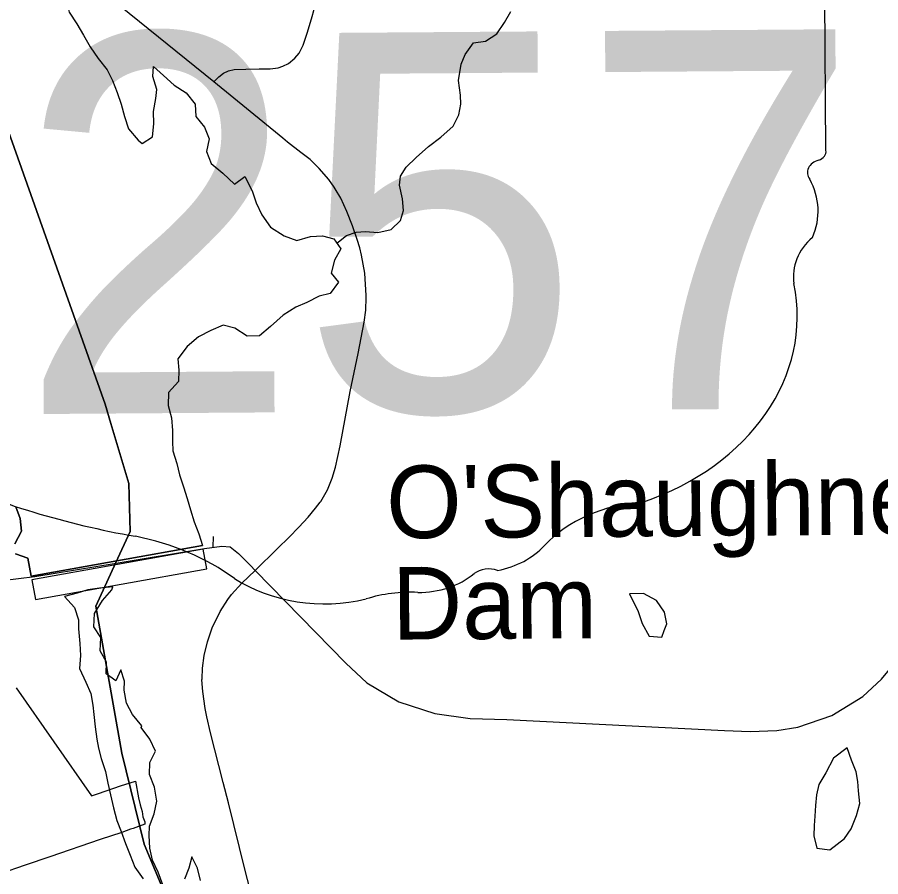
# Model space of a CAD drawing. Extents: x 114604 to 551442, y 316898 to 567001.
# Drawn here: x 170319 to 175079, y 455101 to 459836 of the extents above; entities that cross this region are included whole.
import ezdxf

# ---------------------------------------------------------------- set-up
doc = ezdxf.new("R2010")
doc.units = 0
for name, color, linetype in [('_CIVIL_CONSTRUCTION', 7, 'Continuous'), ('BD_X_Building', 7, 'Continuous'), ('DV_X_County_Line', 7, 'Continuous'), ('GE_P_Alignment_1000_Cardinal_Points', 7, 'Continuous'), ('GE_P_Alignment_100_Stations', 7, 'Continuous'), ('GE_P_Alignment_500_Bearings', 7, 'Continuous'), ('GE_P_Alignment_500_Curve_Data', 7, 'Continuous'), ('GE_P_Alignment_500_Distances', 7, 'Continuous'), ('MT_X_Edge_Line', 7, 'Continuous'), ('PM_P_Cells', 7, 'Continuous'), ('RD_X_GR_Lt', 7, 'Continuous'), ('RD_X_GR_Rt', 7, 'Continuous'), ('VG_X_Tree_Line_Lt', 7, 'Continuous')]:
    doc.layers.add(name, color=color, linetype=linetype)

msp = doc.modelspace()

# ---------------------------------------------------------------- linework, layer by layer
at = {"layer": '_CIVIL_CONSTRUCTION'}
for points in [[(171809.5, 459148.5), (171783.9, 459168.8), (171402.2, 459479.2), (170888.9, 459895.5), (170834.9, 459938.9), (170817.5, 459954.2), (170801.2, 459970.7), (170786.2, 459988.3), (170759.8, 460026.4), (170738.9, 460067.8), (170730.7, 460089.4), (170724, 460111.6), (170718.8, 460134.2), (170697.1, 460524.6)], [(171934, 459051.6), (171882.2, 459090.8), (171809.5, 459148.5)], [(172072.5, 458891), (172067, 458900.2), (172037.4, 458941.2), (171983.2, 459003.3), (171938, 459048.6), (171934, 459051.6)], [(172242.7, 458292.6), (172243.2, 458303.4), (172236, 458425.3), (172216.1, 458524.2), (172207.5, 458565.2), (172193.4, 458610.6), (172167, 458686.6), (172136.9, 458765.9), (172102.9, 458839.9), (172072.5, 458891)], [(171992.6, 457168.6), (172030, 457232.4), (172055.2, 457296), (172073, 457357.1), (172099.1, 457475.1), (172154.2, 457774), (172199.3, 457983.3), (172232, 458156.2), (172240, 458222.2), (172242.7, 458292.6)], [(171630.2, 456788), (172131.2, 456277.9), (172246.5, 456168.6), (172422.5, 456064.3), (172620.6, 456000.6), (172816.3, 455972.8), (173018.5, 455967.5), (174218.4, 455906.5), (174360, 455900.8), (174506, 455906.3), (174622.6, 455925.2), (174808.6, 455989.4), (174980.8, 456094), (175083.5, 456189.1), (175188.2, 456315.6), (175239.1, 456408.1), (175305.4, 456565.8), (175338.2, 456694.1), (175366.2, 456860.5), (175458.4, 457463.2), (175484.3, 457607.1), (175516.9, 457757.9), (175583.1, 457935.8), (175631, 458018.4)], [(171630.2, 456788), (171754.6, 456909.4), (171817.6, 456971.1), (171872.2, 457026.6), (171923.3, 457081), (171963, 457130.5), (171989.9, 457164.1), (171992.6, 457168.6)], [(171337.7, 456190.6), (171339.7, 456249.1), (171350.1, 456319.1), (171368.7, 456394.7), (171394.6, 456471.5), (171437.1, 456561.2), (171480.4, 456628.7), (171500.4, 456655), (171556.7, 456717), (171630.2, 456788)], [(171365, 455981), (171355.1, 456027.4), (171341.8, 456121.6), (171337.5, 456185.3), (171337.7, 456190.6)], [(171454.9, 455620.2), (171383.7, 455893.4), (171365, 455981)], [(172785.3, 451744.5), (172762.2, 451787.7), (172544.6, 452270.4), (172423.6, 452624.8), (172267.6, 453051), (172114.7, 453480), (172037.4, 453708.8), (171899.4, 454074.1), (171677.8, 454736.5), (171574.2, 455142.8), (171484.5, 455506.8), (171454.9, 455620.2)]]:
    msp.add_lwpolyline(points, dxfattribs=at)
at = {"layer": 'DV_X_County_Line'}
msp.add_line((170396.1, 456755.8), (171341.2, 456925), dxfattribs=at)
for points in [[(170431.1, 460604.1), (170469.3, 460538), (170501.6, 460472), (170471.8, 460401.8), (170463.9, 460351.6), (170474.1, 460287.5), (170508.4, 460219.5), (170560.7, 460155.5), (170591, 460095.4), (170597.1, 460045.3), (170591.3, 459983.2), (170589.4, 459931.1), (170605.7, 459863), (170647.9, 459799), (170684.2, 459736.9), (170720.5, 459672.9), (170764.8, 459608.9), (170815.1, 459546.9), (170843.4, 459486.8), (170869.6, 459420.8), (170891.9, 459356.7), (170910.1, 459288.6), (170932.4, 459220.5), (170986.7, 459158.5)], [(170986.7, 459158.5), (171007.9, 459140.1), (171064.4, 459176.1), (171072.9, 459248.2), (171069.4, 459316.3), (171084, 459388.4), (171088.4, 459438.5), (171066.9, 459508.8), (171069.4, 459564.9), (171125, 459514.3), (171184.7, 459461.7), (171250.5, 459419.1), (171300, 459356.6), (171303.5, 459288.4), (171351.1, 459230), (171376.6, 459165.6), (171362.1, 459095.6), (171387.6, 459029.2), (171453.3, 458976.6), (171516.9, 458916), (171573.2, 458957.6), (171614.7, 458879.1), (171636.2, 458812.8), (171667.7, 458746.4), (171715.2, 458679.9), (171791, 458631.2), (171860.8, 458606.6), (171935.1, 458628.1), (172001.2, 458631.6), (172065.2, 458615), (172102.8, 458560.6), (172068.2, 458496.7), (172049.7, 458426.7), (172089.3, 458376.3), (172044.8, 458314.5), (171982.6, 458299), (171916.2, 458263.4), (171854, 458237.9), (171785.6, 458194.3), (171715, 458132.7), (171654.5, 458081.1), (171586.4, 458079.6), (171518.7, 458122.3), (171454.7, 458138.8), (171386.4, 458109.3), (171318.1, 458075.7), (171255.6, 458022.1), (171205, 457954.4), (171210.5, 457892.2), (171208, 457828.1), (171153.5, 457768.4), (171150.9, 457696.2), (171170.4, 457627.9), (171175.9, 457559.7), (171175.4, 457497.6), (171177, 457447.5), (171198.5, 457377.2), (171214.1, 457314.9), (171235.6, 457248.6), (171255.1, 457184.3), (171274.6, 457122), (171294.1, 457055.7), (171319.7, 456989.3), (171341.2, 456925)], [(170310.8, 457138.4), (170335, 457074.4), (170343.2, 457004.2), (170305.3, 456934)], [(170309.5, 456879.9), (170377.8, 456856), (170396.1, 456755.8)], [(170845.5, 456696.8), (170773.3, 456690.6), (170709.1, 456680.5), (170649, 456662.3), (170578.9, 456644), (170635.2, 456584.1), (170657.5, 456516), (170657.6, 456465.9), (170663.9, 456385.7), (170668.1, 456319.6), (170662.3, 456247.4), (170696.6, 456173.3), (170724.9, 456109.2), (170735.1, 456045.1), (170741.2, 455995), (170749.4, 455926.9), (170757.7, 455858.8), (170767.8, 455808.7), (170782, 455752.6), (170806.3, 455680.5), (170818.5, 455616.4), (170832.8, 455552.3), (170849, 455480.2), (170867.3, 455410.1), (170891.5, 455350), (170915.7, 455283.9), (170942, 455219.8), (170968.3, 455153.8), (171012.6, 455089.7)], [(171006.1, 455931.6), (170953.8, 455993.6), (170921.5, 456057.6), (170909.3, 456127.8), (170911.1, 456177.9), (170890.9, 456240), (170863, 456179.8), (170808.8, 456217.7), (170810.6, 456281.8), (170776.3, 456345.9), (170780.1, 456418.1), (170741.8, 456478.1), (170745.6, 456550.3), (170789.5, 456622.5), (170841.5, 456680.8), (170845.5, 456696.8)], [(171122.4, 455056.6), (171096.9, 455125), (171065.4, 455191.4), (171049.9, 455257.7), (171046.4, 455327.8), (171048.8, 455379.9), (171073.4, 455447.9), (171087.9, 455515.9), (171076.5, 455594.2), (171049.1, 455664.6), (171049.6, 455730.7), (171082.1, 455792.6), (171050.6, 455859), (171003, 455923.5), (171006.1, 455931.6)], [(171328.8, 455079.1), (171313.3, 455147.3), (171281.8, 455209.7), (171265.3, 455147.7), (171240.8, 455087.8)]]:
    msp.add_lwpolyline(points, dxfattribs=at)
at = {"layer": 'GE_P_Alignment_1000_Cardinal_Points'}
msp.add_lwpolyline([(171402.2, 459479.2), (171430.6, 459508.2), (171455.5, 459527.3), (171483.7, 459540.9), (171514.1, 459548.6), (171579.1, 459550.6), (171652.6, 459551.3), (171714.3, 459550.8), (171758.4, 459556.9), (171783.7, 459565.5), (171815.3, 459581.9), (171850.1, 459609.6), (171872.7, 459637.2), (171896, 459682.7), (171918.4, 459753.1), (171945.3, 459840.1), (171953.4, 459873.5), (171964.8, 459941.4), (171969.7, 459998.3), (171969.9, 460122.1), (171978.5, 460457.7)], dxfattribs=at)
at = {"layer": 'GE_P_Alignment_100_Stations'}
msp.add_lwpolyline([(170314, 456140.8), (170727.8, 455546.8), (170728.1, 455546.3), (170767, 455559.7), (170887.9, 455601.5), (170970.5, 455627.5), (170987.8, 455534.9), (170997.1, 455497.2), (171007.1, 455460), (171011.8, 455429.9), (171021.7, 455402.6), (171022.8, 455389.3), (170957.7, 455366.8), (170943.7, 455362), (170895.5, 455345), (170775.5, 455305.6), (170499, 455211), (170363.3, 455164.7), (170225, 455117)], dxfattribs=at)
at = {"layer": 'GE_P_Alignment_500_Bearings'}
msp.add_lwpolyline([(168892.8, 456835.9), (169086.8, 456871.2), (169153.8, 456873), (169210.6, 456865.6), (169267.4, 456850.6), (169675.4, 456719.5), (169819.8, 456701.2), (169876.5, 456696.4), (169988.1, 456699.6), (170038.5, 456705.7), (170236.3, 456733.2), (170416.9, 456754.6), (170863.8, 456828.5), (171352.1, 456909.3), (171447.7, 456922.6), (171492.9, 456917.5), (171539.3, 456880.8), (171604.8, 456814.4), (171630.2, 456788)], dxfattribs=at)
at = {"layer": 'GE_P_Alignment_500_Curve_Data'}
for p, q in [((174777.2, 459102.2), (174765.3, 460760.4)), ((174776.7, 459102.6), (174777.2, 459102.2))]:
    msp.add_line(p, q, dxfattribs=at)
for centre, major_axis, start_param, end_param in [((174715.3, 459095.3), (62.2, 0.4), 5.05454, 6.418171), ((174764.7, 458980.3), (89.9, 0.6), 1.883978, 3.671073), ((174194, 458766.6), (539.9, 3.9), 5.934695, 6.695948), ((174990.4, 458409.7), (392.8, 2.8), 2.387724, 3.262537), ((173234.2, 458186.1), (1384.8, 10), 5.101753, 6.440018), ((171834, 460101.4), (3998, 28.8), 4.195995, 4.488959), ((173829.9, 456560.5), (758.4, 5.5), 1.647645, 2.488433), ((170671.5, 456003.6), (1250.9, 9), 0.823519, 1.323588), ((172864.8, 457136.3), (447.4, 3.2), 4.937069, 5.64225), ((172918.7, 456700.9), (119.1, 0.9), 1.147584, 2.315152), ((172015.6, 457238.8), (793.8, 5.7), 4.026481, 4.996735), ((172533.9, 457005.2), (422.9, 3), 4.691044, 5.507374), ((172482.1, 456146.2), (652.2, 4.7), 1.495662, 1.94098)]:
    msp.add_ellipse(centre, major_axis=major_axis, ratio=0.8, start_param=start_param, end_param=end_param, dxfattribs=at)
at = {"layer": 'GE_P_Alignment_500_Distances'}
for points in [[(170250.2, 459264.1), (170803.8, 457703.8), (170835.4, 457597.7), (170933.5, 457267.5), (170941.5, 457002.9), (170862.6, 456831.3), (170751.7, 456590.3), (170896.2, 455781.1), (171019, 455280.7), (171414.9, 454330.3), (171495.6, 453944.8), (171686.4, 453391.5), (171797.2, 453111.3), (172158.3, 452814.9), (172277.6, 452609.1), (172388.6, 452309), (172410.3, 452073.5), (172371.6, 451741.9), (171021.2, 451864.1), (170446.5, 451909.5), (169613.4, 451967.6)], [(180912.9, 451416.4), (178654.1, 451485.6), (177080.5, 451574.7), (176495.7, 451600.3), (175244.6, 451642.6), (172784.1, 451747.3), (172371.6, 451741.9), (172410.3, 452073.5), (172388.6, 452309), (172277.6, 452609.1), (172158.3, 452814.9), (171797.2, 453111.3), (171686.4, 453391.5), (171495.6, 453944.8), (171414.9, 454330.3), (171019, 455280.7), (170896.2, 455781.1), (170751.7, 456590.3), (170862.6, 456831.3), (170941.5, 457002.9), (170933.5, 457267.5), (170835.4, 457597.7), (170803.8, 457703.8), (170250.2, 459264.1)]]:
    msp.add_lwpolyline(points, dxfattribs=at)
at = {"layer": 'MT_X_Edge_Line'}
for points in [[(173886.1, 456456.2), (173900.1, 456493.9), (173887.6, 456557.9), (173843.1, 456621.8), (173770.9, 456661.3), (173694.9, 456658.8)], [(173694.9, 456658.8), (173741.7, 456560.9), (173764.2, 456495), (173802.7, 456425.1), (173872.7, 456419.6), (173886.1, 456456.2)], [(174894.5, 455811.5), (174819, 455752.9), (174775.7, 455672.5), (174738.2, 455608.1), (174724.7, 455551.9), (174719.1, 455493.8), (174715.6, 455433.6), (174712, 455383.5), (174710.4, 455325.4), (174727, 455257.4), (174799, 455247.9), (174839.5, 455279.9)], [(174839.5, 455279.9), (174878.4, 455310.5), (174916, 455364.9), (174945.4, 455437.2), (174962.9, 455503.5), (174956.3, 455573.5), (174951.9, 455625.6), (174943.5, 455677.6), (174917, 455743.6), (174894.5, 455811.5)]]:
    msp.add_lwpolyline(points, dxfattribs=at)
at = {"layer": 'PM_P_Cells'}
for points in [[(172081.4, 458591.6), (172134.9, 458633.5), (172186.8, 458651.9), (172238.7, 458656.3), (172306.7, 458650.7), (172380.5, 458667.3), (172432.1, 458715.7), (172447.6, 458771.9), (172443.1, 458836), (172426.6, 458910), (172432.2, 458960.1), (172463.8, 459010.4), (172517.3, 459062.9), (172586.8, 459123.4), (172654.3, 459176), (172721.8, 459236.6), (172753.3, 459298.9), (172764.9, 459357.1), (172762.5, 459407.1), (172751.9, 459487.2), (172767.1, 459577.4), (172788.7, 459629.7), (172834.2, 459694.1), (172900.1, 459704.5), (172963.7, 459745), (173005.2, 459807.4), (173040.7, 459867.8)], [(171399.8, 456974.3), (171398.1, 456915.4), (171398.2, 456913.9)]]:
    msp.add_lwpolyline(points, dxfattribs=at)
at = {"layer": 'RD_X_GR_Rt'}
for p, q in [((171344.7, 456905.4), (170399.6, 456736.1)), ((171364.1, 456797.1), (171344.7, 456905.4)), ((170419, 456627.9), (171364.1, 456797.1)), ((170399.6, 456736.1), (170419, 456627.9))]:
    msp.add_line(p, q, dxfattribs=at)
at = {"layer": 'VG_X_Tree_Line_Lt'}
msp.add_line((171341.2, 456925), (170396.1, 456755.8), dxfattribs=at)
for points in [[(170431.1, 460604.1), (170469.3, 460538), (170501.6, 460472), (170471.8, 460401.8), (170463.9, 460351.6), (170474.1, 460287.5), (170508.4, 460219.5), (170560.7, 460155.5), (170591, 460095.4), (170597.1, 460045.3), (170591.3, 459983.2), (170589.4, 459931.1), (170605.7, 459863), (170647.9, 459799), (170684.2, 459736.9), (170720.5, 459672.9), (170764.8, 459608.9), (170815.1, 459546.9), (170843.4, 459486.8), (170869.6, 459420.8), (170891.9, 459356.7), (170910.1, 459288.6), (170932.4, 459220.5), (170986.7, 459158.5)], [(170986.7, 459158.5), (171007.9, 459140.1), (171064.4, 459176.1), (171072.9, 459248.2), (171069.4, 459316.3), (171084, 459388.4), (171088.4, 459438.5), (171066.9, 459508.8), (171069.4, 459564.9), (171125, 459514.3), (171184.7, 459461.7), (171250.5, 459419.1), (171300, 459356.6), (171303.5, 459288.4), (171351.1, 459230), (171376.6, 459165.6), (171362.1, 459095.6), (171387.6, 459029.2), (171453.3, 458976.6), (171516.9, 458916), (171573.2, 458957.6), (171614.7, 458879.1), (171636.2, 458812.8), (171667.7, 458746.4), (171715.2, 458679.9), (171791, 458631.2), (171860.8, 458606.6), (171935.1, 458628.1), (172001.2, 458631.6), (172065.2, 458615), (172102.8, 458560.6), (172068.2, 458496.7), (172049.7, 458426.7), (172089.3, 458376.3), (172044.8, 458314.5), (171982.6, 458299), (171916.2, 458263.4), (171854, 458237.9), (171785.6, 458194.3), (171715, 458132.7), (171654.5, 458081.1), (171586.4, 458079.6), (171518.7, 458122.3), (171454.7, 458138.8), (171386.4, 458109.3), (171318.1, 458075.7), (171255.6, 458022.1), (171205, 457954.4), (171210.5, 457892.2), (171208, 457828.1), (171153.5, 457768.4), (171150.9, 457696.2), (171170.4, 457627.9), (171175.9, 457559.7), (171175.4, 457497.6), (171177, 457447.5), (171198.5, 457377.2), (171214.1, 457314.9), (171235.6, 457248.6), (171255.1, 457184.3), (171274.6, 457122), (171294.1, 457055.7), (171319.7, 456989.3), (171341.2, 456925)], [(170305.3, 456934), (170343.2, 457004.2), (170335, 457074.4), (170310.8, 457138.4)], [(170396.1, 456755.8), (170377.8, 456856), (170309.5, 456879.9)]]:
    msp.add_lwpolyline(points, dxfattribs=at)

# ---------------------------------------------------------------- texts
at = {"layer": 'BD_X_Building'}
for s, p in [('s', (172110.7, 458813.4)), ('r', (172110.6, 458813.4)), ('257', (171758.2, 458738.1))]:
    msp.add_text(s, height=1, rotation=0.4127, dxfattribs=at).set_placement(p)
at = {"layer": 'GE_P_Alignment_500_Curve_Data'}
msp.add_text('257', height=2088.31, rotation=0.4127, dxfattribs=at).set_placement((170324.9, 457648.8))
at = {"layer": 'RD_X_GR_Lt'}
for s, height, rotation, p in [("O'Shaughnessy", 400.009, 0.4181, (172354.3, 456964.9)), ('Dam', 400.01, 0.4185, (172386.9, 456406.7))]:
    msp.add_text(s, height=height, rotation=rotation, dxfattribs=at).set_placement(p)

doc.saveas('drawing.dxf')
